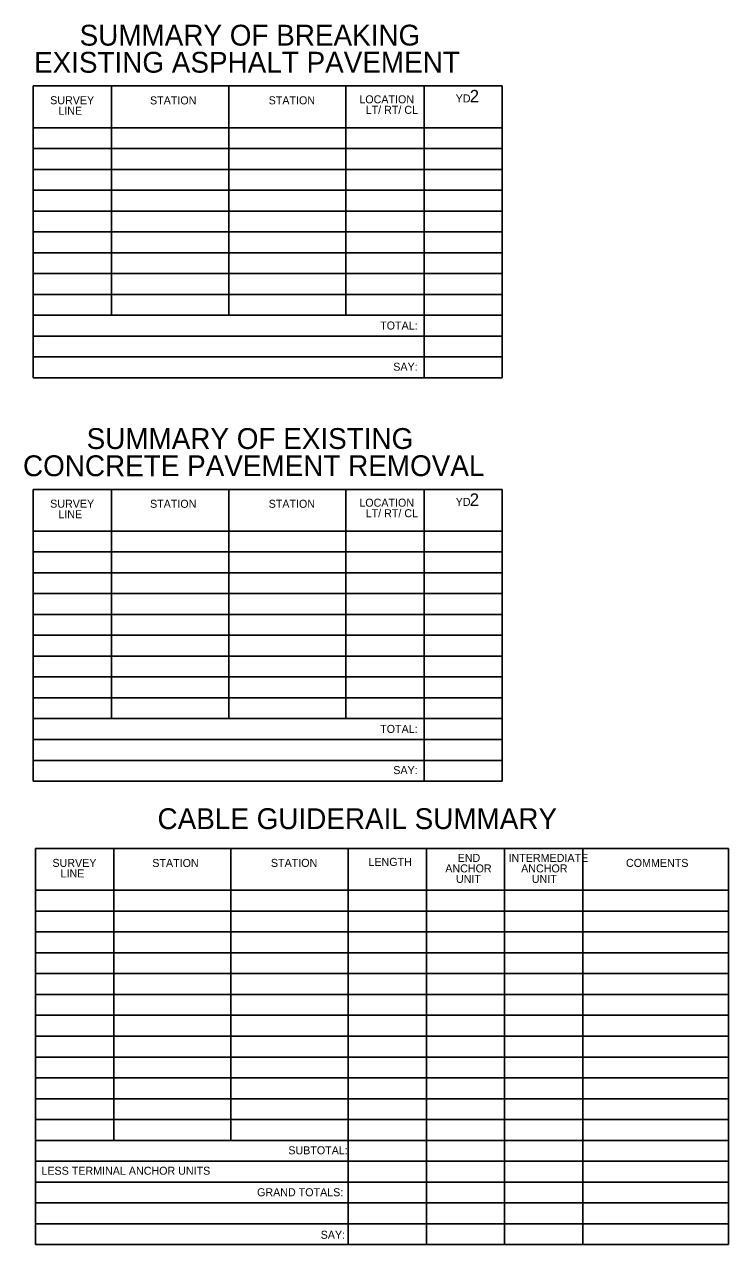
# Model space of a CAD drawing. Extents: x 1729980.3 to 1730027.7, y 539928.4 to 539950.4.
# Drawn here: x 1730019.21 to 1730027.65, y 539932.54 to 539947.18 of the extents above; entities that cross this region are included whole.
import ezdxf

# ---------------------------------------------------------------- set-up
doc = ezdxf.new("R2010")
doc.units = 0
doc.layers.add('Sheet Summary Combination CELL', color=7, linetype='Continuous')
doc.layers.add('Sheet Summary Combination Grid CELL', color=7, linetype='Continuous')

msp = doc.modelspace()

# ---------------------------------------------------------------- linework, layer by layer
at = {"layer": 'Sheet Summary Combination CELL'}
for p, q in [((1730022.138, 539946.436), (1730022.138, 539946.436)), ((1730022.263, 539946.434), (1730022.263, 539946.434)), ((1730022.444, 539946.438), (1730022.444, 539946.438)), ((1730022.556, 539946.436), (1730022.556, 539946.436)), ((1730022.138, 539941.598), (1730022.138, 539941.598)), ((1730022.263, 539941.596), (1730022.263, 539941.596)), ((1730022.444, 539941.6), (1730022.444, 539941.6)), ((1730022.556, 539941.598), (1730022.556, 539941.598)), ((1730022.165, 539937.29), (1730022.165, 539937.29)), ((1730022.29, 539937.288), (1730022.29, 539937.288)), ((1730022.471, 539937.292), (1730022.471, 539937.292)), ((1730022.583, 539937.29), (1730022.583, 539937.29))]:
    msp.add_line(p, q, dxfattribs=at)
at = {"layer": 'Sheet Summary Combination Grid CELL'}
for p, q in [((1730019.313, 539946.437), (1730024.94, 539946.437)), ((1730019.313, 539946.437), (1730019.313, 539942.937)), ((1730020.251, 539946.437), (1730020.251, 539943.687)), ((1730021.658, 539946.437), (1730021.658, 539943.687)), ((1730023.064, 539946.437), (1730023.064, 539943.687)), ((1730024.002, 539946.437), (1730024.002, 539942.937)), ((1730024.94, 539946.437), (1730024.94, 539942.937)), ((1730019.313, 539945.937), (1730024.94, 539945.937)), ((1730019.313, 539945.687), (1730024.94, 539945.687)), ((1730019.313, 539945.437), (1730024.94, 539945.437)), ((1730019.313, 539945.187), (1730024.94, 539945.187)), ((1730019.313, 539944.937), (1730024.94, 539944.937)), ((1730019.313, 539944.687), (1730024.94, 539944.687)), ((1730019.313, 539944.437), (1730024.94, 539944.437)), ((1730019.313, 539944.187), (1730024.94, 539944.187)), ((1730019.313, 539943.937), (1730024.94, 539943.937)), ((1730019.313, 539943.687), (1730024.94, 539943.687)), ((1730019.313, 539943.437), (1730024.94, 539943.437)), ((1730019.313, 539943.187), (1730024.94, 539943.187)), ((1730019.313, 539942.937), (1730024.94, 539942.937)), ((1730019.313, 539941.599), (1730024.94, 539941.599)), ((1730019.313, 539941.599), (1730019.313, 539938.099)), ((1730020.251, 539941.599), (1730020.251, 539938.849)), ((1730021.658, 539941.599), (1730021.658, 539938.849)), ((1730023.064, 539941.599), (1730023.064, 539938.849)), ((1730024.002, 539941.599), (1730024.002, 539938.099)), ((1730024.94, 539941.599), (1730024.94, 539938.099)), ((1730019.313, 539941.099), (1730024.94, 539941.099)), ((1730019.313, 539940.849), (1730024.94, 539940.849)), ((1730019.313, 539940.599), (1730024.94, 539940.599)), ((1730019.313, 539940.349), (1730024.94, 539940.349)), ((1730019.313, 539940.099), (1730024.94, 539940.099)), ((1730019.313, 539939.849), (1730024.94, 539939.849)), ((1730019.313, 539939.599), (1730024.94, 539939.599)), ((1730019.313, 539939.349), (1730024.94, 539939.349)), ((1730019.313, 539939.099), (1730024.94, 539939.099)), ((1730019.313, 539938.849), (1730024.94, 539938.849)), ((1730019.313, 539938.599), (1730024.94, 539938.599)), ((1730019.313, 539938.349), (1730024.94, 539938.349)), ((1730019.313, 539938.099), (1730024.94, 539938.099)), ((1730019.34, 539937.291), (1730027.655, 539937.291)), ((1730019.34, 539937.291), (1730019.34, 539932.541)), ((1730020.278, 539937.291), (1730020.278, 539933.791)), ((1730021.685, 539937.291), (1730021.685, 539933.791)), ((1730023.091, 539937.291), (1730023.091, 539932.541)), ((1730024.029, 539937.291), (1730024.029, 539932.541)), ((1730024.967, 539937.291), (1730024.967, 539932.541)), ((1730025.905, 539937.291), (1730025.905, 539932.541)), ((1730027.655, 539937.291), (1730027.655, 539932.541)), ((1730019.34, 539936.791), (1730027.655, 539936.791)), ((1730019.34, 539936.541), (1730027.655, 539936.541)), ((1730019.34, 539936.291), (1730027.655, 539936.291)), ((1730019.34, 539936.041), (1730027.655, 539936.041)), ((1730019.34, 539935.791), (1730027.655, 539935.791)), ((1730019.34, 539935.541), (1730027.655, 539935.541)), ((1730019.34, 539935.291), (1730027.655, 539935.291)), ((1730019.34, 539935.041), (1730027.655, 539935.041)), ((1730019.34, 539934.791), (1730027.655, 539934.791)), ((1730019.34, 539934.541), (1730027.655, 539934.541)), ((1730019.34, 539934.291), (1730027.655, 539934.291)), ((1730019.34, 539934.041), (1730027.655, 539934.041)), ((1730019.34, 539933.791), (1730027.655, 539933.791)), ((1730019.34, 539933.541), (1730027.655, 539933.541)), ((1730019.34, 539933.291), (1730027.655, 539933.291)), ((1730019.34, 539933.041), (1730027.655, 539933.041)), ((1730019.34, 539932.791), (1730027.655, 539932.791)), ((1730019.34, 539932.541), (1730027.655, 539932.541))]:
    msp.add_line(p, q, dxfattribs=at)

# ---------------------------------------------------------------- texts
at = {"layer": 'Sheet Summary Combination CELL'}
for s, p in [('SUMMARY OF BREAKING', (1730019.869, 539946.921)), ('EXISTING ASPHALT PAVEMENT', (1730019.322, 539946.596)), ('SUMMARY OF EXISTING', (1730019.953, 539942.083)), ('CONCRETE PAVEMENT REMOVAL', (1730019.19, 539941.757)), ('CABLE GUIDERAIL SUMMARY', (1730020.804, 539937.524))]:
    msp.add_text(s, height=0.25, rotation=0.0119, dxfattribs=at).set_placement(p)
for s, p in [('SURVEY', (1730019.516, 539946.218)), ('STATION', (1730020.714, 539946.216)), ('STATION', (1730022.137, 539946.217)), ('LOCATION', (1730023.225, 539946.229)), ('LINE', (1730019.614, 539946.092)), ('LT/ RT/ CL', (1730023.301, 539946.103)), ('TOTAL:', (1730023.475, 539943.516)), ('SAY:', (1730023.632, 539943.022)), ('SURVEY', (1730019.516, 539941.379)), ('STATION', (1730020.714, 539941.378)), ('STATION', (1730022.137, 539941.378)), ('LOCATION', (1730023.225, 539941.391)), ('LINE', (1730019.614, 539941.253)), ('LT/ RT/ CL', (1730023.301, 539941.265)), ('TOTAL:', (1730023.475, 539938.678)), ('SAY:', (1730023.632, 539938.184)), ('END', (1730024.404, 539937.131)), ('INTERMEDIATE', (1730025.015, 539937.131)), ('SURVEY', (1730019.543, 539937.071)), ('LINE', (1730019.641, 539936.945)), ('STATION', (1730020.741, 539937.07)), ('STATION', (1730022.164, 539937.071)), ('LENGTH', (1730023.334, 539937.083)), ('ANCHOR', (1730024.256, 539937.005)), ('ANCHOR', (1730025.166, 539937.005)), ('COMMENTS', (1730026.424, 539937.071)), ('UNIT', (1730024.384, 539936.879)), ('UNIT', (1730025.294, 539936.879)), ('SUBTOTAL:', (1730022.373, 539933.624)), ('LESS TERMINAL ANCHOR UNITS', (1730019.411, 539933.379)), ('GRAND TOTALS:', (1730021.998, 539933.121)), ('SAY:', (1730022.761, 539932.611))]:
    msp.add_text(s, height=0.096, dxfattribs=at).set_placement(p)
at = {"layer": 'Sheet Summary Combination Grid CELL'}
for s, height, p in [('YD', 0.096, (1730024.381, 539946.24)), ('2', 0.15, (1730024.549, 539946.24)), ('YD', 0.096, (1730024.381, 539941.401)), ('2', 0.15, (1730024.549, 539941.401))]:
    msp.add_text(s, height=height, dxfattribs=at).set_placement(p)

doc.saveas('drawing.dxf')
